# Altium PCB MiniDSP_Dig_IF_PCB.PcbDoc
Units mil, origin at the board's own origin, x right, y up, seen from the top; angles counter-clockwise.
Board outline 6400 x 3775 mil, 2 copper layers (Top Layer, Bottom Layer); 95 components, 75 nets, 372 pads, 78 vias.
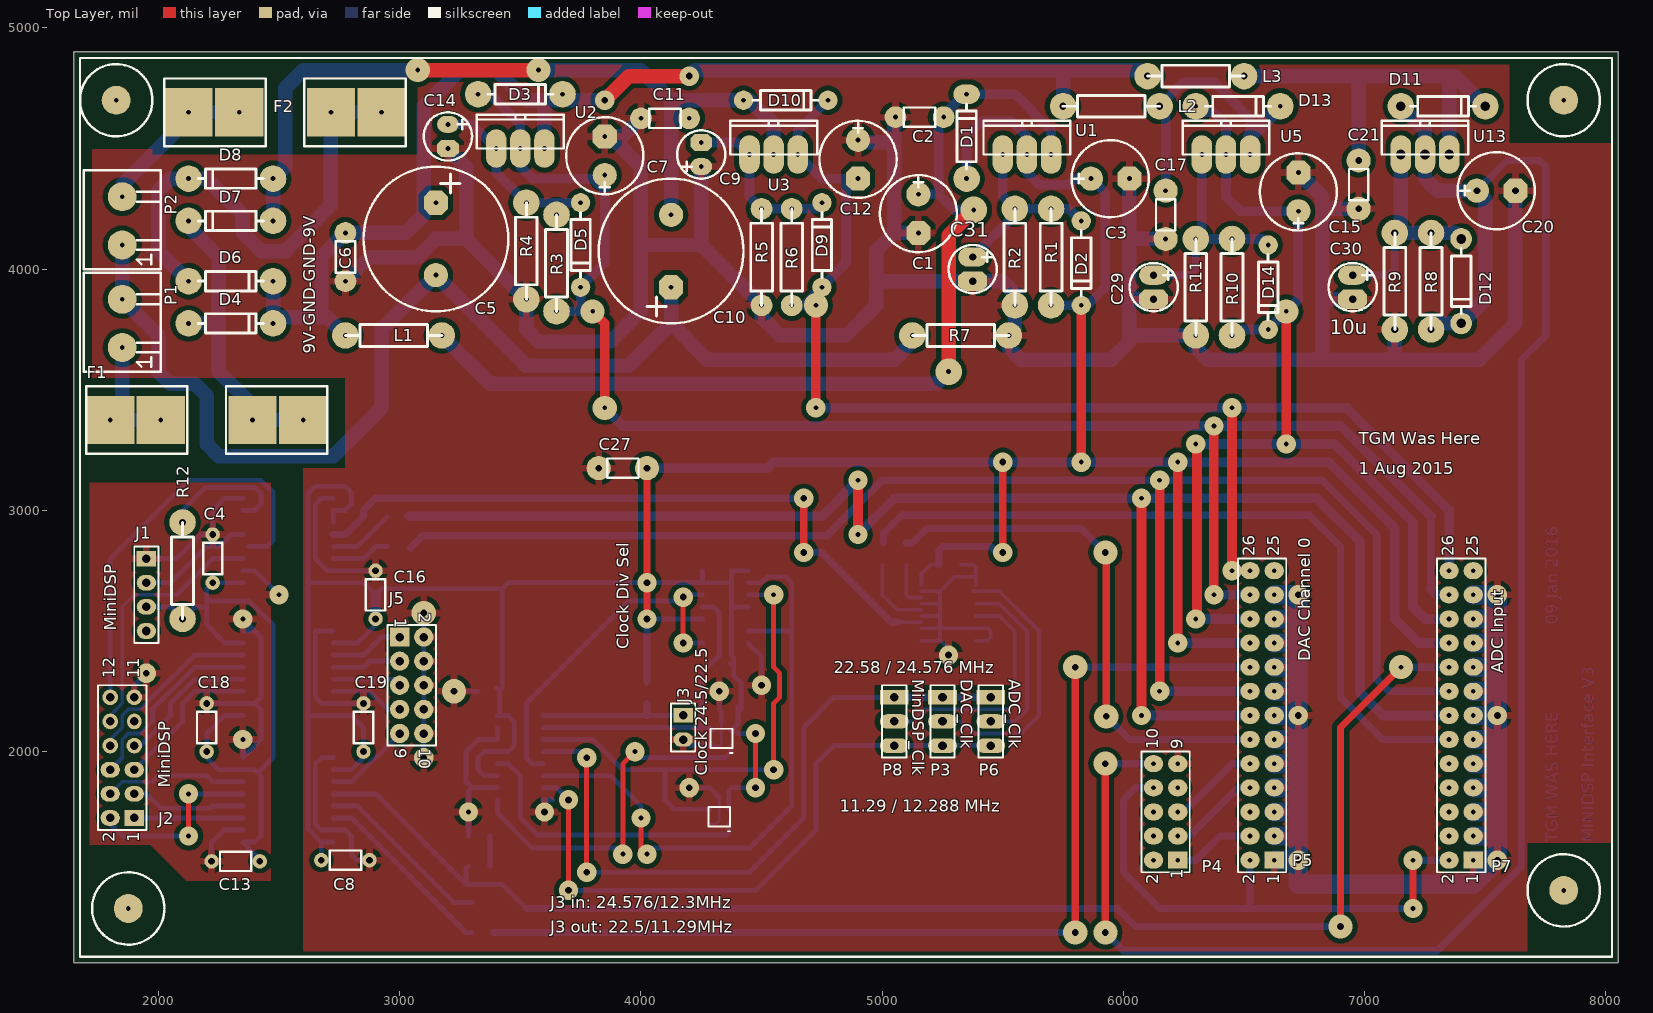
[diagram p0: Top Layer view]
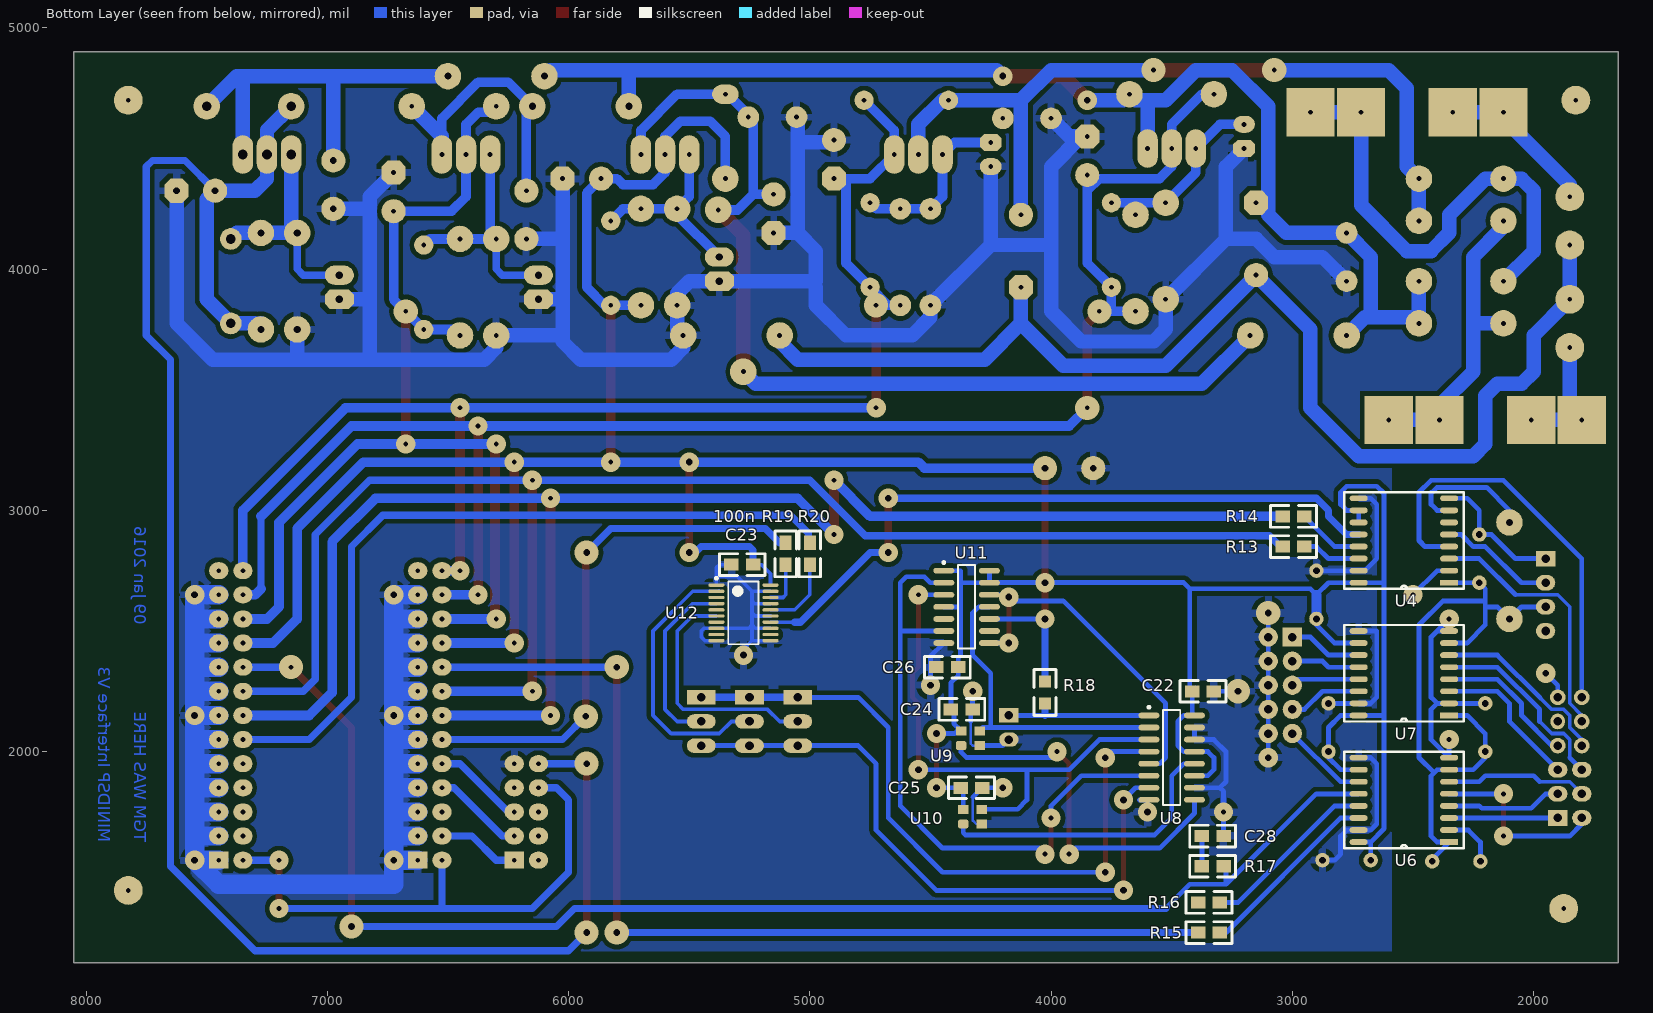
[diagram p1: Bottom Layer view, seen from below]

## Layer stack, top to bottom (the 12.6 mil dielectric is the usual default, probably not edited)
Top Layer: signal copper 1.4
Dielectric: dielectric 12.6, FR-4, Dk 4.8
Bottom Layer: signal copper 1.4

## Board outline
1650,4900 8050,4900 8050,1125 1650,1125

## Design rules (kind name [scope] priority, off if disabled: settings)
Clearance Clearance_poly [(IsRegion)] p1: gap=20
Clearance Clearance_1 [All] p2: gap=10
HoleSize [All] p1: absolutevalues=TRUE maxlimit=120 minlimit=1 maxpercent=80.000 minpercent=20.000
PlaneConnect [All] p1: planeconnectstyle=Relief reliefexpansion=20 reliefentries=4 reliefconductorwidth=30 reliefairgap=10
PolygonConnect [All] p1: connectstyle=Relief reliefconductorwidth=30 reliefentries=4 polygonreliefangle="90 Angle"
RoutingVias [All] p1: holewidth=28 width=50 viastyle="Through Hole" minholewidth=28 minwidth=50 maxholewidth=28 maxwidth=50
SilkscreenOverComponentPads [All] p1: minsilkscreentomaskgap=10
SolderMaskExpansion [All] p1: expansion=4
Width [All] p1: maxlimit=250 minlimit=10 preferedwidth=40
25 further rules are at their usual default settings.

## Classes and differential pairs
component class MiniDSP_DIG_Clk: C22 C23 C24 C25 C26 C27 J3 P3 P6 P8 R18 R19 R20 U8 U9 U10 U11 U12
component class MiniDSP_Dis_IF_PSU: C1 C2 C3 C5 C6 C7 C9 C10 C11 C12 C14 C15 C17 C20 C21 C29 C30 C31 C? D1 D2 D3 D4 D5 D6 D7 D8 D9 D10 D11 D12 D13 D14 D? F1 F2 L1 L2 L3 L? P1 P2 P? R1 R2 R3 R4 R5 R6 R7 R8 R9 R10 R11 R? U1 U2 U3 U5 U13 U?
component class MiniDSP_Dig_IF_Sch: C4 C8 C13 C16 C18 C19 C28 J1 J2 J5 P4 P5 P7 R12 R13 R14 R15 R16 R17 U4 U6 U7

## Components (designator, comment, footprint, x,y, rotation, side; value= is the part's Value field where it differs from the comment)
C1 "47uF" RB.16/.32-PTH#1 5150,4150 r90 top
C2 "100n" AXIAL0.2-pth#1 5255.01,4630.01 r180 top
C3 "47uF" RB.16/.32-PTH#1 6025,4375 r180 top
C4 "100n" AXIAL0.2-pth#2 2225,2900 r270 top
C5 "470uF" RB.3/.6 3150,4275 r90 top
C6 "100n" AXIAL0.2-pth#1 2775,4150 r270 top
C7 "47uF" RB.16/.32-PTH#1 3850,4550 r270 top
C8 "100n" AXIAL0.2-pth#2 2875,1550 r180 top
C9 "10u" RB.1/.2-PTH#1 4250,4425 r270 top
C10 "470uF" RB.3/.6 4125,3925 r270 top
C11 "100n" AXIAL0.2-pth#1 4000,4625 r0 top
C12 "47uF" RB.16/.32-PTH#1 4900,4375 r90 top
C13 "100n" AXIAL0.2-pth#2 2220.27,1545.27 r0 top
C14 "10u" RB.1/.2-PTH#1 3200,4600 r90 top
C15 "47uF" RB.16/.32-PTH#1 6725,4400 r270 top
C16 "100n" AXIAL0.2-pth#2 2900,2750 r270 top
C17 "100n" AXIAL0.2-pth#3 6175,4325 r270 top
C18 "100n" AXIAL0.2-pth#2 2200,2200 r270 top
C19 "100n" AXIAL0.2-pth#2 2850,2200 r270 top
C20 "47uF" RB.16/.32-PTH#2 7625,4325 r180 top
C21 "100n" AXIAL0.2-pth#4 6975,4450 r270 top
C22 "100n" 0805#1 3325,2250 r0 bottom
C23 "100n" 0805#1 5325,2775 r180 bottom
C24 "100n" 0805#1 4325,2175 r0 bottom
C25 "100n" 0805#1 4285,1850 r0 bottom
C26 "100n" 0805#1 4475,2350 r180 bottom
C27 "100n" AXIAL0.2-pth#4 3825,3175 r0 top
C28 "100p" 0805#1 3375,1650 r180 bottom
C29 "10u" RB.1/.2-PTH#2 6125,3975 r90 top
C30 "10u" RB.1/.2-PTH#2 6950,3975 r90 top
C31 "10u" RB.1/.2-PTH#2 5375,4050 r90 top
D1 "1N4004" DIODE0.35-TH#1 5350,4375 r90 top
D2 "1n4001" DIODE0.35-pth#1 5825,4200 r270 top
D3 "1N4004" DIODE0.35-TH#2 3325,4725 r0 top
D4 "1N4004" DIODE0.35-TH#2 2125,3775 r0 top
D5 "1n4001" DIODE0.35-pth#1 3750,4275 r270 top
D6 "1N4004" DIODE0.35-TH#2 2125,3950 r0 top
D7 "1N4004" DIODE0.35-TH#2 2475,4200 r180 top
D8 "1N4004" DIODE0.35-TH#2 2475,4375 r180 top
D9 "1n4001" DIODE0.35-pth#1 4750,3925 r90 top
D10 "1n4001" DIODE0.35-pth#1 4425,4700 r0 top
D11 "1N4004" DIODE0.35-TH#3 7150,4675 r0 top
D12 "1n4001" DIODE0.35-pth#2 7400,4125 r270 top
D13 "1N4004" DIODE0.35-TH#2 6300,4675 r0 top
D14 "1n4001" DIODE0.35-pth#1 6600,4100 r270 top
F1 "5A" FUSE-Small-M205 2600,3375 r270 top
F2 "5A" FUSE-Small-M205 2925,4650 r270 top
J1 "MiniDSP_I/F" HDR1X4 1950,2800 r270 top
J2 "MiniDSP_IO" HDR2X6 1900,1725 r90 top
J3 "CLK_24.5/22.5" HDR1X2 4175,2150 r270 top
J5 "Spare I/O" HDR2X5#1 3000,2475 r270 top
L1 "Ferrite" AXIAL0.4#1 2775,3725 r0 top
L2 "Ferrite" AXIAL0.4#2 5750,4675 r0 top
L3 "Ferrite" AXIAL0.4#2 6100,4800 r0 top
P1 "24VAC" CON2_SCREW 1850,3675 r0 top
P2 "24VAC" CON2_SCREW 1850,4100 r0 top
P3 "DAC_Clk" HDR1X3 5250,2225 r270 top
P4 "To J2 on PIC32" HDR2X5#2 6225,1550 r90 top
P5 "DAC Channel 0" HDR2X13 6625,1550 r90 top
P6 "ADC_Clk" HDR1X3 5450,2225 r270 top
P7 "ADC Input" HDR2X13 7450,1550 r90 top
P8 "MinDSP_Clk" HDR1X3 5050,2225 r270 top
R1 "330" AXIAL0.4#1 5700,4250 r270 top
R2 "560" AXIAL0.4#1 5550,3850 r90 top
R3 "220" AXIAL0.4#1 3650,4225 r270 top
R4 "1K5" AXIAL0.4#1 3525,3875 r90 top
R5 "1K5" AXIAL0.4-pth 4500,4250 r270 top
R6 "220" AXIAL0.4-pth 4625,3850 r90 top
R7 "0R" AXIAL0.4#1 5525,3725 r180 top
R8 "330" AXIAL0.4#2 7275,4150 r270 top
R9 "1K" AXIAL0.4#2 7125,3750 r90 top
R10 "330" AXIAL0.4#1 6450,4125 r270 top
R11 "1K" AXIAL0.4#1 6300,3725 r90 top
R12 "0R" AXIAL0.4#2 2100,2550 r90 top
R13 "100R" 0805#1 2950,2850 r0 bottom
R14 "100R" 0805#1 2950,2975 r0 bottom
R15 "100R" 0805#1 3300,1250 r0 bottom
R16 "100R" 0805#1 3300,1375 r0 bottom
R17 "100R" 0805#1 3375,1525 r180 bottom
R18 "1K" 0805#2 4025,2200 r90 bottom
R19 "100R" 0805#1 5100,2775 r90 bottom
R20 "100R" 0805#1 5000,2775 r90 bottom
U1 "LM317" TO-220-REG#1 5600,4475 r0 top
U2 "LM317" TO-220-REG#1 3500,4500 r0 top
U3 "LM337" TO-220-REG#1 4550,4475 r0 top
U4 "SI8642BB" SOIC16-Wide 2350,2700 r0 bottom
U5 "LM317" TO-220-REG#1 6425,4475 r0 top
U6 "SI8642BB" SOIC16-Wide 2350,1625 r0 bottom
U7 "SI8642BB" SOIC16-Wide 2350,2150 r0 bottom
U8 "74LVC157ADR" D016_N 3500,1975 r180 bottom
U9 "24.576MHz" SMD_XCO 4368.9,2025 r180 bottom
U10 "22.579MHz" SMD_XCO 4360,1700 r180 bottom
U11 "MC74AHC74D" 751A-03_N 4350,2600 r180 bottom
U12 "SN74LVC244APW" PW020_N 5275,2575 r180 bottom
U13 "LM317" TO-220-REG#2 7250,4475 r0 top

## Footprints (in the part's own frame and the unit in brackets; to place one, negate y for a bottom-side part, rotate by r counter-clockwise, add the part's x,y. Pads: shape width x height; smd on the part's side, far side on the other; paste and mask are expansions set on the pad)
751A-03_N [mm] "SOIC, 14-Leads, Body 8.7x3.9mm, Pitch 1.27mm, IPC Medium Density"
  oval 2.2x0.6 smd: 1(-2.4,3.81) 2(-2.4,2.54) 3(-2.4,1.27) 4(-2.4,0) 5(-2.4,-1.27) 6(-2.4,-2.54) 7(-2.4,-3.81) 8(2.4,-3.81) 9(2.4,-2.54) 10(2.4,-1.27) 11(2.4,0) 12(2.4,1.27) 13(2.4,2.54) 14(2.4,3.81)
  silkscreen extent -2.53,-4.4 0.9,4.78, body extent -2,-4.38 2,4.38, height 1.75
0805#1 [mil]
  rect 60x50 smd: 1(0,0) 2(90,0)
  silkscreen extent -50,-45 140,45, body extent -56,-51 146,51, height 10
0805#2 [mil]
  rect 50x50 smd: 1(0,0) 2(90,0)
  silkscreen extent -50,-45 140,45, body extent -56,-51 146,51, height 10
AXIAL0.2-pth#1 [mil]
  round 90 hole 20: 1(0,0) 2(200,0)
  silkscreen extent 35,-40 165,40
AXIAL0.2-pth#2 [mil]
  round 60 hole 28: 1(0,0) 2(200,0)
  silkscreen extent 35,-40 165,40, body extent 30,-45 170,45, height 200
AXIAL0.2-pth#3 [mil]
  round 100 hole 20: 1(0,0) 2(200,0)
  silkscreen extent 35,-40 165,40
AXIAL0.2-pth#4 [mil]
  round 100 hole 28: 1(0,0) 2(200,0)
  silkscreen extent 35,-40 165,40, body extent 30,-45 170,45, height 200
AXIAL0.4#1 [mil]
  round 110 hole 20: 1(0,0) 2(400,0)
  silkscreen extent 0,-45 400,45, body extent 60,-45 340,45, height 120
AXIAL0.4#2 [mil]
  round 110 hole 30: 1(0,0) 2(400,0)
  silkscreen extent 0,-45 400,45, body extent 60,-40 340,40, height 100
AXIAL0.4-pth [mil]
  round 90 hole 20: 1(0,0) 2(400,0)
  silkscreen extent 0,-45 400,45
CON2_SCREW [mil]
  round 120 hole 20: 1(0,0) 2(0,200)
  silkscreen extent -160,-100 160,310, body extent -160,-100 160,310, height 300
D016_N [mm] "SOIC, 16-Leads, Body 9.9x3.9mm, Pitch 1.27mm, IPC Medium Density"
  oval 2.2x0.6 smd: 1(-2.4,4.445) 2(-2.4,3.175) 3(-2.4,1.905) 4(-2.4,0.635) 5(-2.4,-0.635) 6(-2.4,-1.905) 7(-2.4,-3.175) 8(-2.4,-4.445) 9(2.4,-4.445) 10(2.4,-3.175) 11(2.4,-1.905) 12(2.4,-0.635) 13(2.4,0.635) 14(2.4,1.905) 15(2.4,3.175) 16(2.4,4.445)
  silkscreen extent -2.53,-5 0.9,5.42, body extent -2,-5 2,5, height 1.75
DIODE0.35-pth#1 [mil]
  round 80 hole 20: 1(0,0) 2(350,0)
  silkscreen extent 40,-40 310,40
DIODE0.35-pth#2 [mil]
  round 90 hole 40: 1(0,0) 2(350,0)
  silkscreen extent 40,-40 310,40, body extent 65,-40 275,40, height 45
DIODE0.35-TH#1 [mil]
  round 110 hole 20: 1(0,0)
  oval 80x110 hole 20: 2(350,0)
  silkscreen extent 40,-40 310,40
DIODE0.35-TH#2 [mil]
  round 110 hole 20: 1(0,0) 2(350,0)
  silkscreen extent 40,-40 310,40
DIODE0.35-TH#3 [mil]
  round 110 hole 40: 1(0,0) 2(350,0)
  silkscreen extent 40,-40 310,40
FUSE-Small-M205 [mil]
  rect 200x200 hole 20: 1(0,-800) 2(0,0) 3(0,-590) 4(0,-210)
  silkscreen extent -140,-900 140,100
HDR1X2 [mil] "Connector; Header; 2 Position"
  rect 60x80 hole 35.43: 1(0,0)
  oval 59.06x80 hole 35.43: 2(100,0)
  silkscreen extent -50,-50 150,50
HDR1X3 [mil] "Connector; Header; 3 Position"
  rect 60x120 hole 35.43: 1(0,0)
  oval 60x120 hole 35.43: 2(100,0) 3(200,0)
  silkscreen extent -50,-50 250,50
HDR1X4 [mil] "Connector; Header; 4 Position"
  rect 65x80 hole 35.43: 1(0,0)
  oval 65x80 hole 35.43: 2(100,0) 3(200,0) 4(300,0)
  silkscreen extent -50,-50 350,50
HDR2X5#1 [mil] "Connector; Header; 5x2 Position"
  rect 80x80 hole 35.43: 1(0,0)
  round 80 hole 35.43: 2(0,100) 3(100,0) 4(100,100) 5(200,0) 6(200,100) 7(300,0) 8(300,100) 9(400,0) 10(400,100)
  silkscreen extent -50,-50 450,150
HDR2X5#2 [mil] "Connector; Header; 5x2 Position"
  rect 70x80 hole 20: 1(0,0)
  oval 70x80 hole 20: 2(0,100) 3(100,0) 4(100,100) 5(200,0) 6(200,100) 7(300,0) 8(300,100) 9(400,0) 10(400,100)
  silkscreen extent -50,-50 450,150
HDR2X6 [mil] "Connector; Header; 6x2 Position"
  rect 65x80 hole 35.43: 1(0,0)
  oval 65x80 hole 35.43: 2(0,100) 3(100,0) 4(100,100) 5(200,0) 6(200,100)
  round 65 hole 35.43: 7(300,0) 8(300,100) 10(400,100) 11(500,0) 12(500,100)
  oval 65x60 hole 35.43: 9(400,0)
  silkscreen extent -50,-50 550,150
HDR2X13 [mil] "Connector; Header; 13x2 Position"
  rect 70x80 hole 20: 1(0,0)
  oval 70x80 hole 20: 2(0,100) 3(100,0) 4(100,100) 5(200,0) 6(200,100) 7(300,0) 8(300,100) 9(400,0) 10(400,100) 11(500,0) 12(500,100) 13(600,0) 14(600,100) 15(700,0) 16(700,100) 17(800,0) 18(800,100) 19(900,0) 20(900,100) 21(1000,0) 22(1000,100) 23(1100,0) 24(1100,100) 25(1200,0) 26(1200,100)
  silkscreen extent -50,-50 1250,150
PW020_N [mm] "TSOP, 20-Leads, Body 6.5x4.4mm, Pitch 0.65mm, IPC Medium Density"
  oval 1.7x0.35 smd: 1(-2.85,2.925) 2(-2.85,2.275) 3(-2.85,1.625) 4(-2.85,0.975) 5(-2.85,0.325) 6(-2.85,-0.325) 7(-2.85,-0.975) 8(-2.85,-1.625) 9(-2.85,-2.275) 10(-2.85,-2.925) 11(2.85,-2.925) 12(2.85,-2.275) 13(2.85,-1.625) 14(2.85,-0.975) 15(2.85,-0.325) 16(2.85,0.325) 17(2.85,0.975) 18(2.85,1.625) 19(2.85,2.275) 20(2.85,2.925)
  silkscreen extent -2.98,-3.3 1.6,3.77, body extent -2.25,-3.3 2.25,3.3, height 1.2
RB.1/.2-PTH#1 [mil]
  oval 70x90 hole 20: 1(0,0)
  oct 70x90 hole 20: 2(-100,0)
  silkscreen extent -150,-100 50,100
RB.1/.2-PTH#2 [mil]
  oval 80x120 hole 30: 1(0,0)
  oct 80x120 hole 30: 2(-100,0)
  silkscreen extent -150,-100 50,100, body extent -150,-100 50,100, height 300
RB.3/.6 [mil]
  oct 100x100 hole 20: 1(0,0)
  round 100 hole 20: 2(-300,0)
  silkscreen extent -450,-300 150,300, body extent -450,-300 150,300, height 1000
RB.16/.32-PTH#1 [mil]
  round 100 hole 20: 1(160,0)
  oct 100x100 hole 20: 2(0,0)
  silkscreen extent -80,-160 240,160
RB.16/.32-PTH#2 [mil]
  round 100 hole 28: 1(160,0)
  oct 100x100 hole 28: 2(0,0)
  silkscreen extent -80,-160 240,160, body extent -80,-160 240,160, height 540
SMD_XCO [mm] "2.5x2.0mm Xtal Oscillator Module"
  rrect50% 1.1x0.95 smd: 1(-0.1,0)
  rect 1.1x0.95 smd: 2(1.85,0) 3(1.85,1.55) 4(-0.1,1.55)
SOIC16-Wide [mil]
  rect 74.8x24 smd: 1(0,0)
  oval 74.8x24 smd: 2(0,-50) 3(0,-100) 4(0,-150) 5(0,-200) 6(0,-250) 7(0,-300) 8(0,-350) 9(375,-350) 10(375,-300) 11(375,-250) 12(375,-200) 13(375,-150) 14(375,-100) 15(375,-50) 16(375,0)
  silkscreen extent -60,-375 435,25
TO-220-REG#1 [mil]
  oval 85x160 hole 20: 1(-100,0) 2(0,0) 3(100,0)
  silkscreen extent -180,0 180,140
TO-220-REG#2 [mil]
  oval 85x160 hole 40: 1(-100,0) 2(0,0) 3(100,0)
  silkscreen extent -180,0 180,140, body extent -180,0 180,140, height 800

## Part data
C1 C3 C5 C7 C15 C20: library part "CAPACITOR POL"
C2 C4 C6 C8 C11 C13 C16 C17 C18 C19 C21 C27: library part CAP, "Capacitor"
C9 C10 C12 C14 C29 C30 C31: library part CAPACITOR, "Capacitor"
C22 C23 C24 C25 C26 C28: library part CAP
D1 D3 D4 D6 D7 D8 D11 D13: library part DIODE_Numbered
D2 D5 D9 D10 D12 D14: library part DIODE, "Diode"
F1 F2: library part FUSE1
J1: library part "Header 4", "Header, 4-Pin"
J2: library part "Header 6X2", "Header, 6-Pin, Dual row"
J3 P1 P2: library part "Header 2", "Header, 2-Pin"
J5 P4: library part "Header 5X2", "Header, 5-Pin, Dual row"
L1 L2 L3: library part Inductor, "Inductor"
P3 P6 P8: library part "Header 3", "Header, 3-Pin"
P5 P7: library part "Header 13X2", "Header, 13-Pin, Dual row"
R1 R2 R3 R4 R5 R6 R7 R8 R9 R10 R11 R12 R13 R14 R15 R16 R17 R18 R19 R20: library part RES2
U4 U6 U7: "SILICON LABS DIGITAL ISOLATOR, 8NS, WSOIC-16, Element14 P/N 2423200"
U8: library part 74LVQ157M(16), "Low Voltage Quad 2 Channel Multiplexer, Eleement14 P/N: 1236314"
U9: library part XCO, "Xtal Oscllator Module, Element14 P/N: 1842177"
U10: library part XCO, "Xtal Oscllator Module, Element14 P/N: 2405758"
U11: library part MC74AC74D, "Dual D-Type Positive Edge-Triggered Flip-Flop, , Element14 P/N 1749933"
U12: "Octal Buffer/Driver with 3-State Outputs"

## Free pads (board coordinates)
  round 120 hole 20: 0(1825,4700) 0(1875,1350) 0(7825,1425) 0(7825,4700)

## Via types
v1: diameter 80, hole 28, Top Layer to Bottom Layer, 30 vias
v2: diameter 80, hole 20, Top Layer to Bottom Layer, 30 vias
v3: diameter 100, hole 28, Top Layer to Bottom Layer, 9 vias
v4: diameter 100, hole 20, Top Layer to Bottom Layer, 7 vias
v5: diameter 110, hole 20, Top Layer to Bottom Layer, 2 vias

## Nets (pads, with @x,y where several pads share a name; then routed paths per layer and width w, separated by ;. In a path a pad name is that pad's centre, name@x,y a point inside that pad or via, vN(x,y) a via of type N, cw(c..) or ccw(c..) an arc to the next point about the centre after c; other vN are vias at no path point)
5V_PIC: C20.1 D11.1 D12.2 P4.10 R8.2 U13.2 | length 7433
  Top Layer w30: v3(5925,1250) v3(5925,1950)
  Bottom Layer w30: v3(5925,1250) 6000,1175 7300,1175 7650,1525 7650,3625 7750,3725 7750,4425 7725,4450 7590,4450 C20.1 ; v3(5925,1950) P4.10
  Bottom Layer w60: D11.1 7250,4575 U13.2 7250,4375 7300,4325 C20.1 7500,4290 7500,3875 D12.2 7300,3775 R8.2 R8.2@7275,3775
9VAC_1: D4.1 D7.2 F1.2 F1.4 | length 1269.8
  Bottom Layer w60: D4.1 2250,3775 ; D7.2 2125,4175 2250,4050 2250,3575 2390,3435 F1.4 F1.2
9VAC_2: D6.1 D8.2 F2.2 F2.4 | length 1994.4
  Bottom Layer w60: D6.1 2000,4075 2000,4325 2050,4375 D8.2 2200,4375 2350,4225 2350,4150 2425,4075 2525,4075 2715,4265 F2.4 ; F2.4@2750,4650 F2.2@2950,4650
12.3/11.3MHZ: P3.3 P6.3 P8.3 U8.7 | length 2660.8
  Top Layer w20: v1(3700,1425) v1(3700,1800)
  Bottom Layer w20: U8.7 3650,1850 v1(3700,1800) ; v1(3700,1425) 4475,1425 4725,1675 4725,1950 4800,2025 P8.3 P3.3 P6.3
22MHZ_SEL: U8.12 U10.1 | length 1222.9
  Bottom Layer w20: U8.12 3450,1950 3500,1900 3500,1725 3570,1655 4355,1655 4363.94,1663.94 U10.1
24.5_22.5MHZ: P3.1 P6.1 P8.1 U8.4 | length 2875.5
  Top Layer w20: v1(3775,1500) v1(3775,1975)
  Bottom Layer w20: U8.4 3775,2000 v1(3775,1975) ; v1(3775,1500) 4450,1500 4675,1725 4675,2100 4800,2225 P8.1
  Bottom Layer w30: P8.1 P3.1 P6.1
24MHZ_SEL: U8.9 U9.1 | length 1500.4
  Top Layer w20: v2(3925,1575) 3925,1950 v2(3975,2000)
  Bottom Layer w20: U8.9 3405.51,1744.49 3550,1600 v2@3900,1600 ; v2(3975,2000) 4000,1975 4350,1975 4372.83,1997.83 U9.1
+9V: C7.1 D3.1 D5.2 P5.24 P7.24 R3.2 U2.2 | length 6792.1
  Top Layer w40: v4(3800,3825) 3850,3775 v4(3850,3425) ; v2(6375,2650) v2(6375,3350)
  Bottom Layer w30: 7275,2675 7275,2975
  Bottom Layer w40: D3.1 3375,4725 3500,4600 U2.2 3500,4425 3550,4375 3800,4375 3850,4325 ; R3.2 v4(3800,3825) ; 3750,3850 D5.2 3850,4025 3850,4325 ; v4(3850,3425) 3925,3350 v2(6375,3350) 6900,3350 7275,2975 ; C7.1 3850,4325 ; v2(6375,2650) P5.24 ; 7275,2675 7300,2650 P7.24
-9V: C12.2 D9.1 D10.2 P5.26 P7.26 R6.1 U3.3 | length 5491.7
  Top Layer w40: v2(4725,3425) v4(4725,3850) ; v2(6450,2750) v2(6450,3425)
  Bottom Layer w40: v2(4725,3425) 6925,3425 7350,3000 P7.26 ; v4(4725,3850) R6.1 4675,3850 D9.1 4850,4025 4850,4375 4750,4375 U3.3 4650,4575 D10.2 ; v2(6450,2750) P5.26
BCLK: P5.16 P7.16 R13.2 | length 6384.9
  Top Layer w40: v2(6150,2250) v2(6150,3125)
  Bottom Layer w30: R13.2@3045,2845 3095,2895 4770,2895 5000,3125 6825,3125 7050,2900 7050,2300 7100,2250 P7.16
  Bottom Layer w40: v2(6150,2250) P5.16
CLK_11.289: U8.6 U11.2 U11.6 | length 2671.9
  Top Layer w20: v2(4000,1725) 4000,1575 v2(4025,1575)
  Bottom Layer w20: U8.6 3875,1900 4000,1775 v2(4000,1725) ; v2(4025,1575) 4050,1600 4450,1600 4625,1775 4625,2500 ; U11.6 4625,2500 ; U11.2 4500,2700 4525,2725 4600,2725 4625,2700 4625,2500
CLK_12.288: U8.5 U11.8 U11.12 | length 1511.8
  Top Layer w20: v1(4175,2450) v1(4175,2640.47) v1@4175,2650
  Bottom Layer w20: U8.5 3550,1950 3525,1975 3525,2200 3600,2275 3950,2625 4150,2625 v1@4175,2650 ; v1(4175,2450) U11.8 ; v1(4175,2640.47) v1@4175,2650 ; U11.12 v1@4175,2650
CLK_22.597: U8.3 U10.3 U11.3 | length 2186.8
  Top Layer w20: v1(4550,1925) 4550,2200 4575,2225 4575,2325 4550,2350 v2(4550,2650)
  Bottom Layer w20: U8.3 3800,2050 3925,1925 4150,1925 v1(4550,1925) ; 4100,1925 4100,1800 4138.98,1761.02 U10.3 ; U11.3 v2(4550,2650)
CLK_24.576: U8.2 U9.3 U11.11 | length 1293.3
  Bottom Layer w20: U8.2 4250,2100 ; U11.11 4300,2600 4325,2575 4325,2400 4250,2325 4250,2100 ; U9.3 4282.09,2100 4250,2100
DAC_RESET_3.3V_L: P4.8 P5.2 P7.2 | length 2257.8
  Top Layer w30: v2(7200,1350) v2(7200,1550)
  Bottom Layer w30: P4.8 6050,1850 6000,1800 6000,1500 6150,1350 6525,1350 ; P5.2 6525,1350 ; v2(7200,1350) 6525,1350 ; v2(7200,1550) P7.2
DVDD_3.3: C3.1 C8.2 C16.2 C19.2 C22.2 C23.2 C24.2 C25.2 C26.2 C27.2 D1.1 D2.2 P5.20 P7.20 R1.2 R18.2 U1.2 U4.10 U4.11 U4.16 U6.10 U6.16 U7.10 U7.16 U8.11 U8.13 U8.16 U9.4 U10.4 U11.1 U11.4 U11.10 U11.13 U11.14 U12.20 | length 16343
  Top Layer w20: v1(4475,1850) v1(4475,2075)
  Top Layer w30: v1(4025,2550) v1(4025,2700.47) C27.2 ; v1(5500,2825) v1(5500,3200)
  Top Layer w40: v2(5825,3200) D2.2 ; v2(6225,2450) v2(6225,3200)
  Bottom Layer w14: C25.2@4363.94,1838.94 C25.2
  Bottom Layer w15: U12.20 5162.8,2737.8 5200,2775 C23.2
  Bottom Layer w20: C8.2 2675,1625 ; U6.16 2675,1625 ; U6.10 2800,1925 2850,1975 2850,2100 2800,2150 U7.16 2620,2150 ; U7.10 2825,2450 C16.2@2900,2525 ; U4.11 U4.10 2775,3000 2800,3025 2800,3075 2775,3100 2650,3100 2620,3070 2620,2700 ; C22.2@3400,2265 C22.2 ; U8.11 3350,1900 3325,1925 3325,1975 3350,2000 U8.13 3450,2000 3475,2025 3475,2125 3450,2150 U8.16 3415,2159.49 C22.2 ; v1(4025,2550) U11.10 ; 4209.85,2700 U11.13 ; U11.13@4255.51,2700.94 U11.14 ; U10.4 C25.2@4363.94,1838.94 ; C26.2@4370,2365 C26.2 ; C25.2 v1(4475,1850) ; U9.4@4386.81,2100 U9.4 ; C24.2@4402.5,2187.5 4402.5,2115.69 U9.4 ; C24.2 4415,2285 4385,2315 C26.2 ; U11.4 4375,2600 ; U11.1 4375,2750 4375,2700 ; v1(4475,2075) 4400,2075 4388.98,2086.02 U9.4 ; 2620,2150 2620,2700 ; 2620,2150 2620,1680 2675,1625 ; 2620,2700 U4.16 2850,2700 2900,2650 2925,2675 3425,2675 ; C22.2 3425,2260 3425,2675 ; 3425,2675 3450.47,2700.47 v1(4025,2700.47) 4255.04,2700.47 U11.13 ; U11.13 4375,2700 ; 4375,2600 4375,2400 4385,2390 C26.2 ; 4375,2600 4375,2700
  Bottom Layer w30: R18.2 v1(4025,2550) ; C23.2 5235,2835 5250,2850 5450,2850 5475,2825 v1(5500,2825)
  Bottom Layer w40: C16.2 2900,2650 ; C27.2 4525,3175 4550,3200 v1(5500,3200) v2(6225,3200) 6850,3200 7125,2925 7125,2550 7225,2450 P7.20 ; D1.1 5350,4550 5412.5,4612.5 5537.5,4612.5 5600,4550 U1.2 5600,4400 5650,4350 5775,4350 5800,4375 C3.1 5925,4315 5925,3925 5850,3850 D2.2 R1.2 ; v2(6225,2450) P5.20
GND: C1.2 C2.2 C3.2 C6.2 C7.2 C8.1 C9.1 C11.1 C12.1 C14.2 C15.2 C16.1 C17.2 C19.1 C20.2 C21.2 C22.1 C23.1 C24.1 C25.1 C26.1 C27.1 C28.2 C29.2 C30.2 C31.2 J3.2 J5.2 J5.4 J5.6 J5.8 J5.10 P4.9 P5.1 P5.3 P5.5 P5.7 P5.9 P5.11 P5.13 P5.15 P5.17 P5.19 P5.21 P5.23 P7.1 P7.3 P7.5 P7.7 P7.9 P7.11 P7.13 P7.15 P7.17 P7.19 P7.21 P7.23 R2.1 R4.1 R5.2 R7.1 R9.1 R11.1 U4.9 U4.15 U6.9 U6.15 U7.9 U7.15 U8.8 U8.10 U8.14 U8.15 U9.2 U10.2 U11.7 U12.1 U12.8 U12.10 U12.11 U12.13 U12.15 U12.17 U12.19 | length 22408.9
  Bottom Layer w10: U10.2 4310,1700 4323.82,1713.82 4323.82,1811.18 ; U9.2 4325,2025 4332.72,2032.72 4332.72,2125
  Bottom Layer w15: U12.11 5240.16,2459.84 5275,2425 v1(5275,2400) ; U12.13 5225.59,2511.02 5239.57,2525 ; U12.15 5226.77,2562.2 5239.57,2575 ; U12.17 5227.95,2613.39 5239.57,2625 ; U12.19 5239.57,2664.57 ; 5239.57,2464.57 5239.57,2525 ; C23.1 5375,2775 5387.2,2762.8 5387.2,2725 ; U12.10 5434.84,2459.84 5450,2475 5450,2500 5438.98,2511.02 U12.8 5253.54,2511.02 5239.57,2525 ; U12.1 5387.2,2725 ; 5239.57,2525 5239.57,2575 ; 5239.57,2575 5239.57,2625 ; 5239.57,2625 5239.57,2664.57 ; 5239.57,2664.57 5300,2725 5387.2,2725
  Bottom Layer w20: U6.9 2675,1975 2650,1950 2650,1700 2675,1675 U6.15 2775,1675 2800,1650 2800,1575 2825,1550 C8.1 ; U7.9 2650,2500 2650,2225 2675,2200 U7.15 C19.1 ; U4.9 2675,3050 2650,3025 2650,2800 2700,2750 U4.15 C16.1 ; v1(3100,1975) J5.10 J5.8 J5.6 J5.4 J5.2 v3(3100,2575) ; v3(3225,2250) C22.1 ; C28.2 3285,1835 3300,1850 ; U8.10 3300,1850 ; U8.15 U8.14 3325,2050 3275,2000 3275,1875 3300,1850 ; v1@3600,1725 3600,1794.49 U8.8 U8.8@3633.86,1800 ; J3.2 4200,2025 U9.2 ; v1(4200,1850) C25.1 4323.82,1811.18 ; v1(4325,2250) C24.1 4332.72,2167.28 4332.72,2125 ; U11.7 4500,2394.49 v1(4500,2275)
  Bottom Layer w60: C6.2 2875,4050 3075,4050 3150,4125 3275,4125 ; C14.2 3275,4425 3275,4125 ; 4000,4100 4250,4100 ; C11.1 3925,4550 C7.2 3875,4550 4000,4425 4000,3825 3875,3700 3575,3700 3525,3750 R4.1 3275,4125 ; C9.1 4250,4100 ; C12.1 4910,4525 5050,4525 ; 4975,3925 4975,3850 4850,3725 4575,3725 4500,3800 R5.2 4250,4100 ; C2.2 5050,4625 5050,4525 ; C1.2 5050,4150 ; C3.2 6025,4125 ; C29.2 6025,3875 ; C17.2 6025,4125 ; C15.2 6825,4300 6825,4250 ; C30.2 6825,3875 ; C21.2 6825,4250 ; R9.1 7125,3625 ; C20.2 7625,3775 7475,3625 7125,3625 ; 5050,4150 5050,4525 ; 5050,4150 4975,4075 4975,3950 5500,3950 5550,3900 5550,3750 R7.1 5525,3675 5575,3625 5950,3625 6025,3700 6025,3725 ; 6025,3725 6025,3875 ; 6025,3725 R11.1 6300,3675 6350,3625 6825,3625 ; 6025,3875 6025,4125 ; 6825,3625 6825,3875 ; 6825,3625 7125,3625 ; 6825,3875 6825,4250
  Bottom Layer w80: P5.1 v1(6725,1550) ; P5.3 6725,1650 ; P5.5 6725,1750 ; P5.7 6725,1850 ; P5.9 6725,1950 ; P5.11 6725,2050 ; P5.13 v1(6725,2150) ; P5.15 6725,2250 ; P5.17 6725,2350 ; P5.19 6725,2450 ; P5.21 6725,2550 ; P5.23 v1(6725,2650) v1(6725,1550) ; P7.1 v1(7550,1550) ; P7.3 7550,1650 ; P7.5 7550,1750 ; P7.7 7550,1850 ; P7.9 7550,1950 ; P7.11 7550,2050 ; P7.13 v1(7550,2150) ; P7.15 7550,2250 ; P7.17 7550,2350 ; P7.19 7550,2450 ; P7.21 7550,2550 ; P7.23 v1(7550,2650) v1(7550,1550) ; v1(6725,1550) 6725,1450 7450,1450 v1(7550,1550)
  other v1: 3600,1750
  other v2: 3285,1750
I2S_0_1/2: J2.1 U6.3 | length 450
  Bottom Layer w20: J2.1 U6.3
I2S_0_3/4: J2.3 U6.4 | length 479
  Bottom Layer w20: J2.3 1950,1825 2010,1765 2215,1765 2225,1775 U6.4
I2S_0_5/6: J2.5 U7.3 | length 628.6
  Bottom Layer w20: J2.5 2100,2125 2100,2200 2150,2250 U7.3
I2S_0_7/8: J2.7 U7.4 | length 593.2
  Bottom Layer w20: J2.7 1925,2025 2050,2150 2050,2200 2150,2300 U7.4
I2S_I_1/2: J2.2 U6.5 | length 770.7
  Top Layer w20: v2(2125,1650) v2(2125,1825)
  Bottom Layer w20: J2.2 1800,1700 1850,1650 2100,1650 v2(2125,1650) ; v2(2125,1825) U6.5
I2S_I_3/4: J2.4 U6.6 | length 591.4
  Bottom Layer w15: J2.4 1850,1875 1975,1875
  Bottom Layer w20: 1975,1875 2000,1900 2200,1900 2225,1875 U6.6
I2S_I_5/6: J2.6 U7.5 | length 799.3
  Bottom Layer w15: 1850,1975 1850,2050 1875,2075 1925,2075 1975,2125
  Bottom Layer w20: J2.6 1850,1975 ; 1975,2125 1975,2175 2150,2350 U7.5
I2S_I_7/8: J2.8 U7.6 | length 749.3
  Bottom Layer w15: J2.8@1800,2050 1850,2100 1850,2150 1875,2175 1925,2175 1972.5,2222.5
  Bottom Layer w20: J2.8 J2.8@1800,2050 ; 1972.5,2222.5 2150,2400 U7.6
LRCLK: P5.14 P7.14 R14.2 | length 6748.2
  Top Layer w40: v2(4900,2900) v2(4900,3125) ; v2(6075,2150) v2(6075,3050)
  Bottom Layer w40: R14.2 4750,2975 v2(4900,3125) ; v2(4900,2900) 5050,3050 v2(6075,3050) 6800,3050 6980,2870 6980,2245 7075,2150 P7.14 ; v2(6075,2150) P5.14
LRCLK_O: J2.12 U4.4 | length 1715.7
  Bottom Layer w20: J2.12 1800,2800 2125,3125 2425,3125 2475,3075 2475,2875 2450,2850 U4.4@2375,2850
MCLK-LN-ADC: P7.12 R20.2 | length 3167.4
  Bottom Layer w30: R20.2@5005,2865 5005,2905 5080,2980 6770,2980 6900,2850 6900,2225 7075,2050 P7.12
MCLK-LN-DAC: P5.12 R19.2 | length 2207.7
  Top Layer w30: v3(5928.66,2146.34) v3@5928.66,2821.34
  Bottom Layer w30: R19.2 5125,2865 5185,2925 5825,2925 v3(5925,2825) ; v3@5925,2150 v3(5928.66,2146.34) 6025,2050 P5.12
MCLK_0: J2.9
MCLK_MINIDSP_OUT: U4.12 U12.14 | length 2909
  Top Layer w30: v1@4675,2800 v1(4675,2825) v1(4675,3050)
  Bottom Layer w15: 5063.39,2536.61 U12.14
  Bottom Layer w30: U4.12 2775,2900 2850,2975 2850,3000 2900,3050 v1(4675,3050) ; v1@4675,2800 v1(4675,2825) 4750,2825 5038.39,2536.61 5063.39,2536.61
MINIDSP_3.3: C4.2 C13.2 C18.2 J1.3 R12.1 U4.1 U6.1 U6.7 U7.1 U7.7 | length 2736.7
  Bottom Layer w20: J1.3 2050,2600 R12.1 2150,2600 2200,2600 ; 2200,2625 2375,2625 2475,2525 2475,1975 2412.5,1912.5 2425,1900 ; U7.1 2275,2150 2200,2075 2200,1975 2250,1925 U6.7 2400,1925 2425,1900 ; U7.7 2275,2450 2200,2525 2200,2675 C4.2 U4.1 ; C13.2 2420.27,1554.73 U6.1 2400,1625 2425,1650 2425,1900
MINIDSP_GND: C4.1 C13.1 C18.1 J1.1 J2.11 U4.2 U4.8 U6.2 U6.8 U7.2 U7.8 | length 2087.3
  Bottom Layer w20: J2.11 1900,2275 v1(1950,2325) ; J1.1 2075,2800 2175,2900 C4.1 2225,3000 2275,3050 U4.8 ; C18.1 U7.2 2400,2200 ; C13.1 2220.27,1625 2270.27,1675 U6.2 ; v2(2350,2050) U6.8 2425,2050 2425,2175 2400,2200 ; U7.8 2400,2500 ; v2(2350,2550) 2400,2500 ; U4.2 2400,2750 v2(2500,2650) ; 2400,2200 2425,2225 2425,2475 2400,2500
MINIDSP_MCLK: J1.2 U4.5 | length 482.8
  Bottom Layer w20: J1.2 2050,2700 2200,2850 2250,2850 2300,2900 U4.5
N_GND: C5.2 C10.1 P1.2 P2.1 R7.2 | length 5096.3
  Bottom Layer w60: P2.1 P1.2 2000,3725 2000,3575 2050,3525 2150,3525 2200,3475 2200,3275 2250,3225 2725,3225 2925,3425 2925,3750 C5.2 3525,3600 3950,3600 4125,3775 ; C10.1@4125,3900 4125,3775 ; C10.1 4125,3775 ; R7.2 5125,3700 5050,3625 4275,3625 4125,3775
NetC1_1: C1.1 C2.1 D1.2 L1.2 U1.3 | length 4154
  Top Layer w60: v5(5275,3575) 5275,4140.6 v5(5379.7,4245.3)
  Bottom Layer w40: C1.1 5235,4310 ; v5(5379.7,4245.3) 5299.7,4245.3 5235,4310 ; U1.3 5700,4575 5550,4725 5340.65,4725 5255.01,4639.36 C2.1 5235,4610 5235,4310
  Bottom Layer w60: L1.2 3375,3525 5225,3525 v5(5275,3575)
NetC9_2: C9.2 D9.2 R5.1 R6.2 U3.1 | length 751.8
  Bottom Layer w40: C9.2 4400,4525 U3.1 4450,4300 R5.1 4725,4250 D9.2 ; R6.2 R6.2@4625,4275
NetC10_2: C10.2 C11.2 D7.1 D8.1 D10.1 U3.2 | length 3295
  Top Layer w60: v4(3075,4825) v4(3575,4825)
  Bottom Layer w60: D7.1 D8.1 2525,4425 2525,4550 2525,4750 2600,4825 v4(3075,4825) ; v4(3575,4825) 4000,4825 4125,4700 ; C10.2 4125,4625 4125,4700 ; D10.1 4200,4700 4125,4700 ; D10.1@4450,4700 4550,4600 U3.2
NetC14_1: C14.1 D5.1 R3.1 R4.2 U2.1 | length 793.2
  Bottom Layer w40: C14.1 3300,4600 U2.1 3400,4400 R4.2 D5.1 ; R3.1 R3.1@3650,4275
NetC17_1: C17.1 D13.2 L2.2 U5.3 | length 1220
  Bottom Layer w40: C17.1 6175,4700 6250,4775 6375,4775 6525,4625 U5.3
  Bottom Layer w60: U5.3 6525,4550 D13.2
NetC21_1: C21.1 D11.2 L3.2 U13.3 | length 1737.1
  Bottom Layer w60: L3.2 7375,4800 ; C21.1 6975,4800 ; U13.3 7350,4775 7375,4800 ; D11.2 7375,4800
NetC28_1: C28.1 R17.1 | length 125
  Bottom Layer w20: R17.1 C28.1
NetC29_1: C29.1 D14.1 R10.1 R11.2 U5.1 | length 981.1
  Bottom Layer w30: C29.1 6275,3975 6300,4000 R11.2
  Bottom Layer w40: U5.1 6325,4150 R11.2 R10.1 6575,4125 D14.1
NetC30_1: C30.1 D12.1 R8.1 R9.2 U13.1 | length 956.1
  Bottom Layer w30: C30.1 7100,3975 7125,4000 R9.2
  Bottom Layer w60: U13.1 7150,4175 R9.2 R8.1 7375,4150 D12.1
NetC31_1: C31.1 D2.1 R1.1 R2.2 U1.1 | length 813.9
  Bottom Layer w40: C31.1 5550,4225 R2.2 ; U1.1 5500,4300 R2.2 ; D2.1 5775,4250 R1.1 R2.2
NetF1_1: F1.1 F1.3 P1.1 | length 530.7
  Bottom Layer w60: P1.1 1850,3425 F1.1 F1.3
NetF2_1: F2.1 F2.3 P2.2 | length 684.3
  Bottom Layer w60: P2.2 1850,4350 2150,4650 F2.3@2360,4650
NetJ3_1: J3.1 R18.1 U8.1 | length 630.5
  Bottom Layer w20: U8.1 4025,2150 J3.1
  Bottom Layer w30: 4025,2150 R18.1
NetP3_2: P3.2 U12.2 | length 1145.4
  Bottom Layer w15: P3.2 5325,2125 5375,2075 5575,2075 5650,2150 5650,2500 5484.84,2665.16 5376.85,2665.16 5376.24,2665.77 U12.2@5375,2665.77
NetP6_2: P6.2 U12.4 | length 755.5
  Bottom Layer w15: U12.4 5486.61,2613.39 5600,2500 5600,2175 5550,2125 P6.2
NetP8_2: P8.2 U12.6 | length 1019.6
  Bottom Layer w15: P8.2 5125,2125 5175,2175 5525,2175 5550,2200 5550,2500 5487.8,2562.2 U12.6
NetR12_2: R12.2 U4.7 | length 558
  Bottom Layer w20: R12.2 2100,3000 2195,3095 2400,3095 2420,3075 2425,3075 2425,3025 2400,3000 U4.7
NetR13_1: R13.1 U4.14 | length 245.7
  Bottom Layer w20: U4.14 2850,2800 2900,2850 R13.1
NetR14_1: R14.1 U4.13 | length 276.8
  Bottom Layer w20: U4.13 2825,2850 R14.1
NetR15_1: R15.1 U6.14 | length 771.8
  Bottom Layer w20: U6.14 2800,1725 3275,1250 R15.1
NetR16_1: R16.1 U6.13 | length 740.7
  Bottom Layer w20: U6.13 2825,1775 3225,1375 R16.1
NetR19_1: R19.1 U12.18 | length 192.4
  Bottom Layer w15: R19.1 5100,2650 5111.02,2638.98 U12.18
NetR20_1: R20.1 U12.16 | length 313.6
  Bottom Layer w15: R20.1 5000,2650 5062.2,2587.8 U12.16
POS_UNREG: C5.1 C6.1 D3.2 D4.2 D6.2 L1.1 L2.1 L3.1 U2.3 | length 5250.3
  Top Layer w60: v1(3850,4700) 3950,4800 v1(4200,4800)
  Bottom Layer w60: D4.2 D6.2 ; D4.2@2475,3800 2700,3800 L1.1 ; 2675,3800 2675,4050 C6.1 3025,4150 3100,4225 3100,4675 3250,4825 3400,4825 3525,4700 3600,4700 ; U2.3 3600,4700 ; v1(3850,4700) 3700,4700 D3.2 3650,4700 3600,4700 ; v1(4200,4800) 4225,4825 6075,4825 L3.1 ; L2.1 5750,4825
SCLK_O: J2.10 U4.3 | length 1078.6
  Bottom Layer w15: J2.10@1800,2150 1850,2200 1850,2600 1900,2650 2075,2650
  Bottom Layer w20: J2.10 J2.10@1800,2150 ; 2075,2650 2225,2800 U4.3
SDATA_IN0: P7.18 R17.2 U6.12 | length 5860.5
  Top Layer w30: v3(6900,1275) 6900,2100 v4(7150,2350)
  Bottom Layer w20: U6.12 2900,1825 3275,1450 ; R17.2 3275,1515 3275,1450 ; 3525,1350 3425,1450 3275,1450
  Bottom Layer w30: 3525,1350 5975,1350 6050,1275 v3(6900,1275) ; v4(7150,2350) P7.18
SDATA_IN1: J5.9 U6.11 | length 357.8
  Bottom Layer w20: U6.11 2800,1875 J5.9
SDATA_IN2: J5.3 U7.12 | length 285.4
  Bottom Layer w20: U7.12 2850,2350 2875,2375 J5.3
SDATA_IN3: J5.1 U7.11 | length 306.1
  Bottom Layer w20: U7.11 2850,2400 2925,2475 J5.1
SDATA_OUT0: P5.18 R15.2 | length 4235
  Top Layer w30: v3(5800,1250) v3(5800,2350)
  Bottom Layer w30: R15.2 v3(5800,1250) ; v3(5800,2350) P5.18
SDATA_OUT1: R16.2
SDATA_OUT2: J5.7 U7.14 | length 306.1
  Bottom Layer w20: U7.14 2875,2250 2950,2175 J5.7
SDATA_OUT3: J5.5 U7.13 | length 285.4
  Bottom Layer w20: U7.13 2975,2300 J5.5
SPARE: J1.4
SPI_CS: P4.1 P5.4 | length 341.4
  Bottom Layer w30: P4.1 6300,1550 6400,1650 P5.4
SPI_SCLK: P4.3 P5.8 | length 382.8
  Bottom Layer w30: P4.3 6275,1650 6475,1850 P5.8
SPI_SDO: P4.5 P5.10 | length 382.8
  Bottom Layer w30: P4.5 6250,1750 6450,1950 P5.10
SPI_SDO0: P5.6
VA: C15.1 D13.1 D14.2 P5.22 P7.22 R10.2 U5.2 | length 4541.1
  Top Layer w40: v2(6300,2550) 6305,2570 6305,3270 v2(6300,3275) ; v2(6675,3275) v4(6675,3825)
  Bottom Layer w40: v2(6300,2550) P5.22 ; v2(6300,3275) 6875,3275 7200,2950 7200,2600 7250,2550 P7.22 ; D13.1 6325,4650 6375,4650 6425,4600 6425,4300 6485,4240 C15.1 6725,3875 D14.2 6475,3750 R10.2
VDD: 
pads on no net: P4.2 P4.4 P4.6 P4.7 P5.25 P7.4 P7.6 P7.8 P7.10 P7.25 U4.6 U11.5 U11.9 U12.3 U12.5 U12.7 U12.9 U12.12

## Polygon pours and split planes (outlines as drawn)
GND on Bottom Layer "BottomLayer-GND" (solid, remove dead copper, pour order 1000): 7587.93,4846.8 7587.93,4521.8 8012.93,4521.8 8012.93,1621.8 7662.93,1621.8 7662.93,1171.8 2587.93,1171.8 2587.93,3196.8 1712.93,3196.8 1712.93,4496.8 2012.93,4496.8 2012.93,4846.8
MINIDSP_GND on Top Layer "BottomLayer-No Net" (solid, remove dead copper, pour order 1000): 2465.39,1464.46 2465.39,3114.46 1715.39,3114.46 1715.39,1614.46 1965.39,1614.46 2115.39,1464.46
GND on Top Layer "TopLayer-GND" (solid, remove dead copper, pour order 1001): 7599.69,4846.74 7599.69,4521.74 8024.69,4521.74 8024.69,1621.74 7674.69,1621.74 7674.69,1171.74 2599.69,1171.74 2599.69,3196.74 1724.69,3196.74 1724.69,4496.74 2024.69,4496.74 2024.69,4846.74

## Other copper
Top Layer:
  pour cut-out: 1650,3550 2775,3550 2775,3175 1650,3175
  pour cut-out: 1975,4875 1975,4475 3075,4475 3075,4875
Bottom Layer:
  text "09 Jan 2016" at 7800,2525 h50 r90
  text "TGM WAS HERE" at 7800,1625 h50 r90
  text "MINIDSP Interface V3" at 7950,1625 h50 r90

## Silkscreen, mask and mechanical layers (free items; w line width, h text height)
Top Overlay:
  circle w10: c1875,1350 r150
  circle w10: c7825,1425 r150
  circle w10: c7825,4700 r150
  circle w10: c1825,4700 r150
  lines w10: 1675,1150 1675,4875 8025,4875 8025,1150 1675,1150
  text "9V-GND-GND-9V" at 2650,3650 h50 r90
  text "TGM Was Here" at 6975,3275 h50
  text "1 Aug 2015" at 6975,3150 h50
  text "MiniDSP" at 1825,2500 h50 r90
  text "Clock Div Sel" at 3950,2425 h50 r90
  text "22.58 / 24.576 MHz" at 4800,2325 h50
  text "Clock 24.5/22.5" at 4275,1900 h50 r90
  text "MiniDSP" at 2050,1850 h50 r90
  text "11.29 / 12.288 MHz" at 4825,1750 h50
  text "J3 in: 24.576/12.3MHz" at 3625,1350 h50
  text "J3 out: 22.5/11.29MHz" at 3625,1250 h50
